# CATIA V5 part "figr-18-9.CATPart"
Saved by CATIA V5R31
Part number: Part1
Bounding box of the stored display mesh (mm): x -125 to 125, y -70.235 to 70.235, z 0 to 30
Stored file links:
  D:\PROJECTS\Project 2021\US EDITION\CATIA V5 6R 2021\Resources\Part Files\c18_catia_v6_6r2021_prt\figr-18-9.CATPart
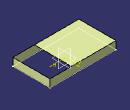
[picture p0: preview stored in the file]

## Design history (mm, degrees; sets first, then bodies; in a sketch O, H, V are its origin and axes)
Body1 (main body)
  Sketch1 on xy-plane, origin (0, 0, 0), H (1, 0, 0), V (0, 1, 0)
    line L1 (125, 70.235) -> (125, -70.235)
    line L2 (125, -70.235) -> (-125, -70.235)
    line L3 (-125, -70.235) -> (-125, 70.235)
    line L4 (-125, 70.235) -> (125, 70.235)
    length L2 = 250
    length L3 = 140.47
    vertical: L1 V, L3 V
    horizontal: L2 H, L4 H
    equidistance: L1 L3 O, L2 L4 O
  Extrude1: Element1 Sketch1, Lim1 30, Lim2 0
  DatumSurface1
